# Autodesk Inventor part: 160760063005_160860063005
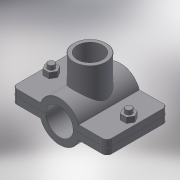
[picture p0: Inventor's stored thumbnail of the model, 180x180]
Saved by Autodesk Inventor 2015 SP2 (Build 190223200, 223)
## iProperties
Created: 2017-05
Part Number: 160760063005_160860063005
Material: Generic
Description: PLASSON SADDLE 63-1/2"
Document SubType Name: Modeling
Designer: KIM
Density: 1 g/cm^3
Appearance: Default
Author: KIM
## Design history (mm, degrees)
derived "16076.ipt"
feature "Solid1::16076.ipt"
feature "Solid2::16076.ipt"
tag "TaggingFeature1"
body "Solid1"
other parameters: "d0" = 78.75, "d1" = 116, "d2" = 31.5, "d3" = 63, "d4" = 84, "d5" = 0, "d6" = 5.8, "d7" = 116, "d8" = 0.1, "d10" = 0, "d11" = 0.63, "d14" = 24.2203, "d20" = 0.63, "d23" = 0.63, "d37" = 8, "d38" = 39.5, "d39" = 0, "d40" = 3, "d41" = 5, "d42" = 0, "d43" = 6, "d44" = 3, "d45" = 0, "d46" = 0.63, "d51" = 58, "d52" = 18.631, "d53" = 18, "d54" = 0, "d55" = 16, "d57" = 0, "d58" = 68.04, "d60" = 0, "d63" = 8, "d66" = 68, "d_" = 63, "B_" = 16, "G_" = 18.631, "A_" = 58, "L_" = 116, "L_1" = 84, "l_2" = 18
